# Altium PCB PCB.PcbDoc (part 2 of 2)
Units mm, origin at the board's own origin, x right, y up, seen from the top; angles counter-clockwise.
Board outline 40.89 x 35.18 mm, 4 copper layers (Top Layer, Signal Layer 1, Signal Layer 2, Bottom Layer), stack 1.554 mm thick; 53 components, 28 nets, 142 pads, 33 vias.
Unrouted connection lines stored in the file: 4.
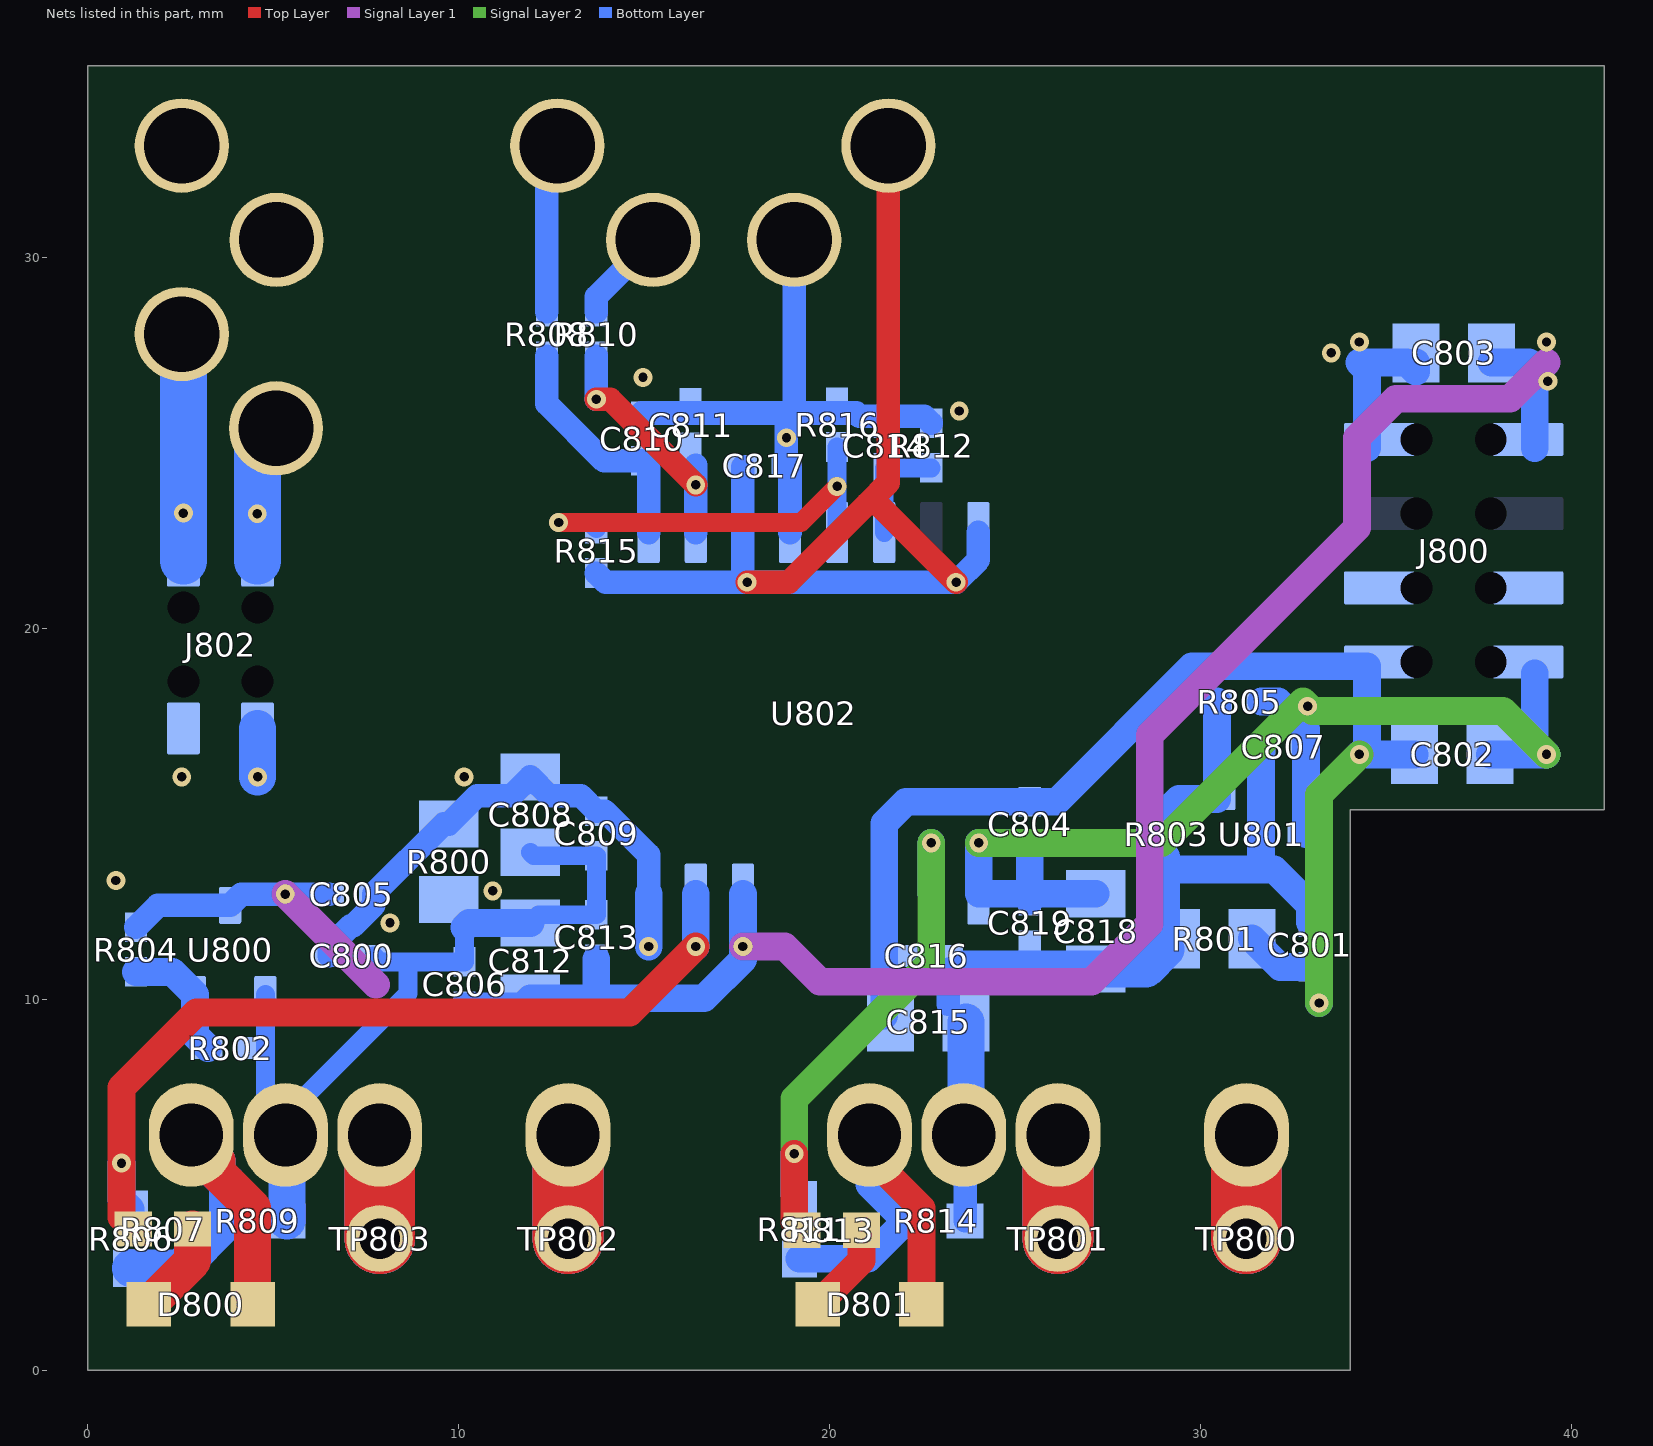
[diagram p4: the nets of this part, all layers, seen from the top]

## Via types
v1: diameter 0.508, hole 0.254, Top Layer to Bottom Layer, 33 vias

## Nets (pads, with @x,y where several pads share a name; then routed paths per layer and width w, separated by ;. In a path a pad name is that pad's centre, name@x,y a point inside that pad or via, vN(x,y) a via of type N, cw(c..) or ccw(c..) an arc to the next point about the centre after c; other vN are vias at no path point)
5Vp: C817.1 J802.1 J802.@4.582,20.571 pad.1@5.08,25.4 pad.1@21.59,33.02 R815.2 U802.3 U802.8 | length 34.7
  Top Layer w0.635: v1(17.78,21.249) 18.901,21.249 21.02,23.368 ; pad.1@21.59,33.02 21.59,23.938 21.02,23.368 ; v1(23.414,21.249) 21.295,23.368 21.02,23.368
  Bottom Layer w0.635: R815.2@13.716,21.498 13.965,21.249 v1(23.414,21.249) 24.017,21.852 U802.8@24.017,22.591 ; v1@17.667,21.39 U802.3@17.667,22.591 C817.1@17.667,24.363
  Bottom Layer w1.27: J802.1@4.582,21.831 pad.1@4.582,24.902
  other v1: 4.572,23.098
5Vs: J800.5 pad.1@35.83,21.098
+VA: C800.1 C803.1 C805.1 C808.1 C809.1 J800.1 pad.1@35.83,25.098 R800.2 U802.16 | length 18.5
  Bottom Layer w0.635: C800.1@6.512,11.176 6.512,11.408 7.098,11.993 7.167,11.993 7.712,12.538 C805.1@7.712,12.842 9.603,14.732 R800.2@9.738,14.732 10.5,15.494 11.43,15.494 C808.1@11.938,16.002 12.446,15.494 13.3,15.494 C809.1@13.716,15.078 13.948,15.078 15.127,13.899 U802.16@15.127,12.842
  Bottom Layer w0.75: v1(15.127,11.43) U802.16@15.127,12.842 ; J800.1@34.494,24.868 34.494,26.974 34.29,27.178 35.564,27.178 35.814,26.928 C803.1@35.814,27.178
  other v1: 8.154,12.065 10.15,16.002 33.528,27.432 34.29,27.727
+VB: C801.1 C802.1 C804.1 C815.1 C816.1 J800.7 pad.1@35.83,19.098 R801.2 U802.11 | length 33.7
  Signal Layer 2 w0.75: v1(33.203,9.906) 33.203,15.521 v1(34.29,16.608)
  Bottom Layer w0.75: C815.1@21.477,9.572 U802.11@21.477,12.842 21.477,14.746 22.063,15.332 C804.1@25.4,15.332 26.127,15.332 29.779,18.984 34.497,18.984 34.497,18.796 34.497,16.815 ; R801.2@31.394,11.643 32.156,10.881 C801.1@32.949,10.881 33.203,10.627 v1(33.203,9.906) ; v1(34.29,16.608) C802.1@35.776,16.608
-VA: C803.2 C805.2 C806.2 C812.2 C813.2 J800.2 pad.1@37.83,25.098 R804.1 U800.3 U802.14 | length 56.6
  Signal Layer 1 w0.75: v1(5.33,12.842) 7.772,10.4 ; v1(17.667,11.43) 18.796,11.43 19.746,10.48 27.064,10.48 28.636,12.052 28.636,17.132 34.224,22.72 34.224,25.146 35.276,26.198 38.352,26.198 39.332,27.178
  Bottom Layer w0.635: R804.1@1.303,11.945 1.895,12.537 U800.3@3.843,12.537 4.147,12.842 v1(5.33,12.842) C805.2@6.512,12.842
  Bottom Layer w0.75: C806.2@10.16,9.814 11.719,9.814 C812.2@11.938,10.033 13.716,10.033 ; C813.2@13.716,11.084 13.716,10.033 ; U802.14@17.667,12.842 v1(17.667,11.43) 17.667,11.083 16.617,10.033 13.716,10.033 ; C803.2@37.846,27.178 38.862,27.178 39.014,27.026 J800.2@39.014,24.868
  other v1: 0.762,13.208 39.37,26.67 39.332,27.727
-VB: C802.2 C804.2 C807.2 C818.2 C819.2 J800.8 pad.1@37.83,19.098 R805.1 U801.3 U802.9 | length 31.4
  Signal Layer 2 w0.75: v1(24.028,14.224) 28.956,14.224 32.766,18.034 33.02,17.78 38.16,17.78 v1(39.332,16.608)
  Bottom Layer w0.75: v1(24.028,14.224) 24.028,12.852 C819.2@25.4,12.852 ; C819.2@25.4,12.665 C819.2@25.4,12.852 ; C804.2@25.4,14.132 C819.2@25.4,12.852 ; C818.2@27.178,12.852 C819.2@25.4,12.852 ; R805.1@31.648,18.034 32.103,18.034 32.848,17.288 U801.3@32.848,14.455 ; C802.2@37.808,16.608 v1(39.332,16.608) ; 39.017,16.763 J800.8@39.017,18.796
  other v1: 32.893,17.907
Coma: C800.2 C806.1 C808.2 C809.2 C812.1 C813.1 pad.1@5.334,6.35 R800.1 R802.2 R809.1 U800.1 | length 22.9
  Bottom Layer w0.508: U800.1@4.793,10.137 4.793,6.891 pad.1@5.334,6.35 5.334,6.858 8.636,10.16 8.636,11.014 ; C800.2@7.712,11.176 7.874,11.014 8.636,11.014 ; 10.16,11.938 C806.1@10.16,11.014 8.636,11.014 ; C812.1@11.938,12.065 12.157,12.284 C813.1@13.716,12.284 C809.2@13.716,13.878 12.03,13.878 C808.2@11.938,13.97
  Bottom Layer w0.75: 10.16,11.938 10.287,12.065 C812.1@11.938,12.065
  Bottom Layer w1: pad.1@5.334,6.35 5.372,6.312 R809.1@5.372,4.031
  other v1: 10.922,12.929
Comb: C801.2 C807.1 C815.2 C816.2 C818.1 C819.1 pad.1@23.622,6.35 R801.1 R803.2 R814.1 U801.1 | length 21.7
  Bottom Layer w0.635: C815.2@23.206,9.875 23.206,10.82 ; R814.1@23.66,4.031 pad.1@23.66,6.312
  Bottom Layer w0.75: R801.1@29.075,11.355 R803.2@29.075,13.855 ; 29.425,13.505 U801.1@30.448,13.505 31.991,13.505 32.949,12.547 C801.2@32.949,12.081 ; 31.633,13.864 C807.1@31.633,16.821
  Bottom Layer w1: 23.622,10.82 C818.1@27.178,10.82 28.54,10.82 R801.1@29.075,11.355 ; pad.1@23.683,6.411 C815.2@23.683,9.398
NetC810_1: C810.1 R808.2 U802.1 | length 6.5
  Bottom Layer w0.635: R808.2@12.383,27.34 12.383,26.064 13.925,24.522 C810.1@14.947,24.522 15.127,24.342 U802.1@15.127,22.591
NetC811_1: C811.1 R810.2 U802.2 | length 6.6
  Top Layer w0.635: v1(13.716,26.184) 14.089,26.184 v1(16.397,23.876)
  Bottom Layer w0.635: v1(13.716,26.184) R810.2@13.716,27.34 ; U802.2@16.397,22.591 v1(16.397,23.876) 16.397,24.405
NetC814_1: C814.1 R812.2 U802.6 | length 3
  Bottom Layer w0.508: U802.6@21.477,22.591 21.477,24.322 C814.1@21.489,24.334 R812.2@22.747,24.334
NetD800_1: D800.1 R807.2 | length 2.5
  Top Layer w1: D800.1@1.648,1.778 2.832,2.962 R807.2@2.832,3.81
NetD801_1: D801.1 R813.2 | length 2.5
  Top Layer w0.75: D801.1@19.682,1.778 20.866,2.962 R813.2@20.866,3.777
NetR802_1: R802.1 R804.2 U800.2 | length 3.4
  Bottom Layer w0.75: R804.2@1.303,10.745 2.285,10.745 U800.2@2.893,10.137 2.893,9.041 R802.1@3.243,8.691
NetR803_1: R803.1 R805.2 U801.2 | length 4.1
  Bottom Layer w0.75: R803.1@29.075,15.055 29.425,15.405 U801.2@30.448,15.405 R805.2@30.448,18.034
NetR806_1: R806.1 R807.1 U802.15 | length 23.8
  Top Layer w0.75: R807.1@1.232,3.81 0.914,4.128 v1(0.914,5.588) 0.914,7.631 2.935,9.652 14.619,9.652 v1(16.397,11.43)
  Bottom Layer w0.75: v1(0.914,5.588) 0.914,4.599 R806.1@1.157,4.356 ; v1(16.397,11.43) U802.15@16.397,12.842
NetR811_1: R811.1 R813.1 U802.10 | length 14.5
  Top Layer w0.75: v1(19.05,5.842) 19.05,3.993 R813.1@19.266,3.777
  Signal Layer 2 w0.75: v1(19.05,5.842) 19.05,7.315 22.747,11.012 v1(22.747,14.224)
  Bottom Layer w0.75: R811.1@19.05,4.751 v1(19.05,5.842) ; U802.10@22.747,12.842 v1(22.747,14.224)
NetR815_1: R815.1 R816.2 U802.5 | length 11.3
  Top Layer w0.508: v1(12.7,22.86) 19.233,22.86 v1(20.207,23.834)
  Bottom Layer w0.508: v1(12.7,22.86) 13.554,22.86 R815.1@13.716,22.698 ; U802.5@20.207,22.591 v1(20.207,23.834) R816.2@20.207,24.895
PGND: C810.2 C811.2 C814.2 C817.2 J802.3 J802.@2.582,20.571 pad.1@2.54,27.94 pad.1@19.05,30.48 R812.1 R816.1 U802.4 | length 21.7
  Bottom Layer w0.635: C810.2@14.947,25.722 14.947,25.812 20.721,25.812 20.811,25.722 22.559,25.722 R812.1@22.747,25.534 ; C817.2@18.842,24.384 18.842,25.766 ; U802.4@18.937,22.591 C817.2@18.937,24.335 ; 19.05,25.974 pad.1@19.05,30.48
  Bottom Layer w1.27: J802.3@2.582,21.831 pad.1@2.582,27.898
  other v1: 2.582,23.114 18.842,25.146 23.5,25.866 14.974,26.771
SGND: J800.6 pad.1@37.83,21.098
VDA: pad.1@31.242,6.35 TP800.1 | length 11.2
  Top Layer w1.905: TP800.1@31.242,3.556 pad.1@31.242,6.35
  Signal Layer 1 w1.905: TP800.1@31.242,3.556 pad.1@31.242,6.35
  Signal Layer 2 w1.905: TP800.1@31.242,3.556 pad.1@31.242,6.35
  Bottom Layer w1.905: TP800.1@31.242,3.556 pad.1@31.242,6.35
VDB: pad.1@12.954,6.35 TP802.1 | length 11.2
  Top Layer w1.905: TP802.1@12.954,3.556 pad.1@12.954,6.35
  Signal Layer 1 w1.905: TP802.1@12.954,3.556 pad.1@12.954,6.35
  Signal Layer 2 w1.905: TP802.1@12.954,3.556 pad.1@12.954,6.35
  Bottom Layer w1.905: TP802.1@12.954,3.556 pad.1@12.954,6.35
Vg1: J802.2 J802.@4.582,18.571 pad.1@5.093,30.48 pad.1@12.663,33.02 R808.1 | length 5.5
  Bottom Layer w0.635: R808.1@12.383,28.54 pad.1@12.383,32.74
  Bottom Layer w1: v1(4.582,16.002) J802.2@4.582,17.311
Vg2: J802.4 J802.@2.582,18.571 pad.1@2.54,33.02 pad.1@15.247,30.48 R810.1 | length 2.6
  Bottom Layer w0.635: R810.1@13.716,28.54 13.716,28.949 pad.1@15.247,30.48
  other v1: 2.54,16.002
VGA: D800.2 pad.1@2.794,6.35 R806.2 R809.2 | length 11.1
  Top Layer w1: pad.1@2.794,6.35 3.491,5.653 3.491,5.333 4.448,4.376 D800.2@4.448,1.778
  Bottom Layer w1: R806.2@1.157,2.756 2.497,2.756 R809.2@3.772,4.031 3.772,5.052 3.491,5.333 3.491,5.653 pad.1@2.794,6.35
VGB: D801.2 pad.1@21.082,6.35 R811.2 R814.2 | length 10.6
  Top Layer w0.75: pad.1@21.082,5.772 22.482,4.372 D801.2@22.482,1.778
  Bottom Layer w0.75: R811.2@19.191,3.01 21.039,3.01 R814.2@22.06,4.031 21.082,5.009 pad.1@21.082,6.35
VSA: pad.1@26.162,6.35 TP801.1 | length 11.2
  Top Layer w1.905: TP801.1@26.162,3.556 pad.1@26.162,6.35
  Signal Layer 1 w1.905: TP801.1@26.162,3.556 pad.1@26.162,6.35
  Signal Layer 2 w1.905: TP801.1@26.162,3.556 pad.1@26.162,6.35
  Bottom Layer w1.905: TP801.1@26.162,3.556 pad.1@26.162,6.35
VSB: pad.1@7.874,6.35 TP803.1 | length 11.2
  Top Layer w1.905: TP803.1@7.874,3.556 pad.1@7.874,6.35
  Signal Layer 1 w1.905: TP803.1@7.874,3.556 pad.1@7.874,6.35
  Signal Layer 2 w1.905: TP803.1@7.874,3.556 pad.1@7.874,6.35
  Bottom Layer w1.905: TP803.1@7.874,3.556 pad.1@7.874,6.35
pads on no net: J800.3 J800.4 U802.7

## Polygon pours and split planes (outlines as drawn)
-VB on Bottom Layer "-VB" (solid, pour order 72): 31.598,18.288 33.274,18.288 33.782,17.78 33.782,14.322 33.43,13.97 32.634,13.97 32.283,14.32 32.283,17.081 31.648,17.716
-VB on Bottom Layer "-VB" (solid, pour order 70): 37.592,19.558 37.084,19.05 37.084,15.621 37.592,15.113 39.878,15.113 40.386,15.621 40.386,19.05 39.878,19.558
+VB on Bottom Layer "+VB" (solid, pour order 64): 22.098,8.382 20.828,8.382 20.574,8.636 20.574,16.255 21.082,16.763 26.122,16.763 26.67,17.311 26.67,19.294 27.188,19.812 35.814,19.812 36.322,19.304 36.322,15.621 35.814,15.113 34.923,15.113 34.036,16 34.036,17.907 33.401,18.542 30.16,18.542 29.779,18.161 29.798,18.142 29.798,16.082
Comb on Bottom Layer "COMB" (solid, pour order 62): 23.116,3.302 22.862,3.556 22.86,3.556 22.86,4.031 22.86,11.472 23.128,11.74 26.276,11.74 31.356,16.821 32.151,16.821 32.848,16.123 32.848,14.185 33.528,13.505 33.528,11.759 33.249,11.481 31.293,11.481 27.94,8.128 25.4,8.128 24.638,7.366 24.638,3.56 24.384,3.306
+VB on Bottom Layer "+VB" (solid, pour order 60): 30.988,12.446 30.734,12.192 30.734,10.414 31.496,9.652 33.528,9.652 33.782,9.906 33.782,10.668 32.004,12.446
-VB on Bottom Layer "-VB" (solid, pour order 58): 23.876,12.192 27.649,12.192 27.94,12.483 27.94,13.716 27.114,14.541 24.182,14.541 23.876,14.235
VGB on Bottom Layer "VGB" (solid, pour order 56): 18.542,3.556 18.288,3.302 18.288,1.778 18.542,1.524 21.844,1.524 22.606,2.286 22.606,4.826 22.098,5.334 22.098,6.999 21.477,7.62 20.758,7.62 20.066,6.928 20.066,4.106 19.516,3.556
VGA on Bottom Layer "VGA" (solid, pour order 54): 2.032,7.874 1.778,7.62 1.778,3.589 1.524,3.335 1.232,3.335 1.016,3.119 1.016,2.286 1.27,2.032 3.893,2.032 4.147,2.286 4.147,5.312 3.048,6.411 3.048,7.62 2.794,7.874
-VA on Bottom Layer "-VA" (solid, pour order 46): 9.906,8.89 9.652,9.144 9.652,10.16 9.906,10.414 12.192,10.414 12.954,11.176 17.007,11.176 17.272,11.441 17.272,13.247 17.487,13.462 17.855,13.462 17.855,13.387 18.034,13.208 18.034,10.414 16.51,8.89
+VA on Bottom Layer "+VA" (solid, pour order 44): 15.24,11.176 15.494,11.43 15.494,15.755 14.993,16.256 9.652,16.256 8.128,14.732 8.128,13.97 5.893,11.735 5.893,11.084 6.101,10.876 13.716,10.876 14.016,11.176
Coma on Bottom Layer "Coma" (solid, pour order 42): 5.093,3.302 4.839,3.556 4.826,3.556 4.826,5.08 4.443,5.463 4.443,6.479 4.318,6.604 4.318,10.185 4.733,10.6 6.927,10.6 9.393,13.066 10.011,13.066 11.281,14.336 13.477,14.336 13.97,13.843 13.97,12.288 13.037,11.355 11.401,11.355 10.46,10.414 9.319,10.414 6.373,7.467 6.373,3.583 6.096,3.306
-VA on Bottom Layer "-VA" (solid, pour order 40): 0.752,13.716 0.508,13.472 0.508,11.684 0.762,11.43 5.294,11.43 6.31,12.446 6.762,12.446 6.858,12.542 6.858,13.462 6.604,13.716
Vg2 on Bottom Layer "Vg2" (solid, pour order 0): 3.048,15.748 2.794,15.494 0.762,15.494 0.254,16.002 0.254,33.274 1.524,34.544 3.545,34.544 4.053,34.036 4.053,32.514 1.482,29.943 1.482,19.727 3.048,18.161
5Vp on Bottom Layer "5Vp" (solid, pour order 6): 6.096,26.924 6.604,26.416 6.604,21.577 5.093,20.066 4.026,20.066 3.772,20.32 3.772,26.114 4.582,26.924
PGND on Bottom Layer "PGND" (solid, pour order 14): 3.556,29.471 4.064,28.963 4.064,28.086 4.064,26.694 3.556,26.186 3.556,20.314 3.308,20.066 2.017,20.066 1.763,20.32 1.763,26.191 1.27,26.683 1.27,28.978 1.763,29.471
PGND on Bottom Layer "PGND" (solid, pour order 26): 17.018,32.004 16.764,31.75 16.764,29.968 14.478,27.682 14.478,25.795 14.873,25.4 23.465,25.4 23.648,25.582 23.648,28.422 20.066,32.004
-VA on Bottom Layer "-VA" (solid, pour order 74): 39.878,24.384 40.378,24.884 40.386,27.94 39.878,28.448 37.338,28.448 37.084,28.194 37.084,24.638 37.338,24.384
+VA on Bottom Layer "+VA" (solid, pour order 76): 36.322,28.451 36.576,28.197 36.576,24.892 36.068,24.384 33.541,24.384 33.02,24.905 33.02,27.94 33.528,28.448
-VB on Signal Layer 2 "-VB" (solid, pour order 68): 39.624,15.487 39.878,15.741 39.878,17.78 39.116,18.542 37.846,18.542 36.322,20.066 29.576,20.066 26.274,16.764 23.876,16.764 23.622,16.51 23.622,13.712 23.876,13.458 29.178,13.458 31.242,15.521
+VB on Signal Layer 2 "+VB" (solid, pour order 66): 32.848,17.018 31.478,15.648 31.478,10.178 32.004,9.652 33.528,9.652 33.782,9.906 33.782,15.24 34.036,15.494 34.544,15.494 34.798,15.748 34.798,16.764 34.544,17.018
-VA on Signal Layer 2 "-VA" (solid, pour order 52): 0.762,13.716 0.508,13.462 0.508,11.929 0.756,11.681 5.336,11.681 5.593,11.938 5.588,11.943 5.588,13.458 5.33,13.716
+VA on Signal Layer 2 "+VA" (solid, pour order 50): 7.62,11.726 7.366,11.98 7.366,13.208 8.128,13.97 8.128,14.392 9.992,16.256 10.668,16.256 10.922,16.002 10.922,14.646 8.636,12.36 8.636,12.065 8.297,11.726
Coma on Signal Layer 2 "Coma" (solid, pour order 48): 5.093,3.237 4.839,3.491 4.826,3.491 4.826,5.015 4.443,5.398 4.443,6.414 4.318,6.539 4.318,8.669 6.184,10.535 6.927,10.535 9.393,13.001 10.011,13.001 10.218,13.208 11.318,13.208 11.684,12.841 11.684,12.146 9.887,10.349 9.319,10.349 6.373,7.402 6.373,3.518 6.096,3.241
Vg2 on Signal Layer 2 "Vg2" (solid, pour order 2): 3.048,15.739 2.794,15.485 0.762,15.485 0.254,15.993 0.254,33.265 1.524,34.535 3.545,34.535 4.053,34.027 4.053,32.505 1.482,29.934 1.482,19.719 3.048,18.152
5Vp on Signal Layer 2 "5Vp" (solid, pour order 12): 6.096,26.924 6.604,26.416 6.604,21.577 5.093,20.066 4.026,20.066 3.772,20.32 3.772,26.114 4.582,26.924
PGND on Signal Layer 2 "PGND" (solid, pour order 20): 3.556,29.471 4.064,28.963 4.064,28.086 4.064,26.694 3.556,26.186 3.556,20.314 3.308,20.066 2.017,20.066 1.763,20.32 1.763,26.191 1.27,26.683 1.27,28.978 1.763,29.471
5Vp on Signal Layer 2 "5Vp" (solid, pour order 24): 20.574,34.544 20.066,34.036 20.066,23.302 19.125,22.361 17.281,22.361 17.018,22.098 17.018,21.082 17.272,20.828 23.622,20.828 23.876,21.082 23.876,34.036 23.368,34.544
PGND on Signal Layer 2 "PGND" (solid, pour order 30): 17.018,32.004 16.764,31.75 16.764,29.968 14.478,27.682 14.478,25.795 14.873,25.4 23.465,25.4 23.648,25.582 23.648,28.422 20.066,32.004
NetR811_1 on Signal Layer 2 "R811_1" (solid, pour order 78): 22.098,14.732 21.844,14.478 21.844,11.671 18.288,8.115 18.288,5.588 18.542,5.334 19.558,5.334 19.812,5.588 19.812,7.14 23.368,10.696 23.368,14.48 23.116,14.732
-VA on Signal Layer 1 "-VA" (solid, pour order 36): 1.125,14.097 0.506,13.479 0.506,12.702 0.508,11.671 3.035,9.144 19.812,9.144 20.32,9.652 27.686,9.652 30.48,12.446 30.48,18.288 34.804,22.612 34.804,24.898 35.56,25.654 37.084,25.654 37.338,25.4 37.338,24.384 37.592,24.13 40.132,24.13 40.64,24.638 40.64,27.94 40.132,28.448 35.657,28.448 30.226,23.017 30.226,21.457 27.178,18.409 27.178,14.097 25.133,12.052 21.616,12.052 19.572,14.097
Vg1 on Signal Layer 1 "Vg1" (solid, pour order 4): 6.096,32.004 6.599,31.501 6.604,29.438 6.122,28.956 4.572,28.956 3.81,29.718 2.038,29.718 1.784,29.464 1.482,29.162 1.482,19.727 2.921,18.288 5.08,18.288 5.33,18.034 5.33,15.998 4.826,15.494 0.753,15.494 0.254,15.993 0.254,31.505 0.753,32.004
5Vp on Signal Layer 1 "5Vp" (solid, pour order 10): 6.096,26.924 6.604,26.416 6.604,21.577 5.093,20.066 4.026,20.066 3.772,20.32 3.772,26.114 4.582,26.924
PGND on Signal Layer 1 "PGND" (solid, pour order 18): 3.556,29.471 4.064,28.963 4.064,28.086 4.064,26.694 3.556,26.186 3.556,20.314 3.308,20.066 2.017,20.066 1.763,20.32 1.763,26.191 1.27,26.683 1.27,28.978 1.763,29.471
PGND on Signal Layer 1 "PGND" (solid, pour order 28): 17.018,32.004 16.764,31.75 16.764,29.968 14.478,27.682 14.478,25.795 14.873,25.4 23.465,25.4 23.648,25.582 23.648,28.422 20.066,32.004
+VA on Top Layer "+VA" (solid, pour order 38): 34.798,28.448 35.306,27.94 35.306,25.394 34.804,24.892 34.804,22.612 30.48,18.288 30.48,12.446 27.686,9.652 20.066,9.652 17.78,11.938 16.256,11.938 14.478,10.16 7.112,10.16 6.122,11.15 6.122,13.351 6.487,13.716 7.874,13.716 8.154,13.996 8.154,14.758 9.652,16.256 17.413,16.256 21.604,12.065 25.121,12.065 27.178,14.122 27.178,18.288 30.226,21.336 30.226,22.62 33.02,25.414 33.02,27.94 33.531,28.451
Vg1 on Top Layer "Vg1" (solid, pour order 34): 6.096,32.027 6.599,31.525 6.604,29.461 6.122,28.979 4.572,28.979 3.81,29.741 2.038,29.741 1.784,29.487 1.482,29.185 1.482,19.751 2.921,18.311 5.08,18.311 5.33,18.057 5.33,16.021 4.826,15.517 0.753,15.517 0.254,16.017 0.254,31.528 0.753,32.027
5Vp on Top Layer "5Vp" (solid, pour order 8): 6.096,26.924 6.604,26.416 6.604,21.577 5.093,20.066 4.026,20.066 3.772,20.32 3.772,26.114 4.582,26.924
PGND on Top Layer "PGND" (solid, pour order 16): 3.556,29.471 4.064,28.963 4.064,28.086 4.064,26.694 3.556,26.186 3.556,20.314 3.308,20.066 2.017,20.066 1.763,20.32 1.763,26.191 1.27,26.683 1.27,28.978 1.763,29.471
5Vp on Top Layer "5Vp" (solid, pour order 22): 20.574,34.544 20.066,34.036 20.066,23.302 19.125,22.361 17.281,22.361 17.018,22.098 17.018,21.082 17.272,20.828 23.622,20.828 23.876,21.082 23.876,34.036 23.368,34.544
NetR806_1 on Top Layer "R806_1" (solid, pour order 32): 0.508,3.048 0.254,3.302 0.254,8.89 1.524,10.16 14.478,10.16 16.256,11.938 16.764,11.938 17.018,11.684 17.018,10.414 15.494,8.89 3.302,8.89 1.778,7.366 1.778,3.339 1.487,3.048

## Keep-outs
Keep-Out Layer:
  text ".Layer_Name" at 14.656,-21.806 h1.52

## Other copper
Top Layer:
  text ".Layer_Name" at 14.656,-21.806 h1.52
Bottom Layer:
  text ".Layer_Name" at 14.656,-21.806 h1.52

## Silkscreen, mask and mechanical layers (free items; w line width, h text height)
Top Overlay:
  lines w0.254: 0.538,-0.302 3.332,-0.302 ; 1.016,14.097 7.874,14.097 7.874,21.336 7.112,21.336 7.112,14.986 1.016,14.986 1.016,14.097 ; 7.112,22.352 7.112,35.179 7.874,35.179 7.874,22.352 7.112,22.352 ; 10.191,17.272 26.162,17.272 26.162,23.368 25.146,23.368 25.146,18.288 10.191,18.288 10.191,17.272
  text "PMP22002 RevA" at 5.842,8.467 h2.75
  text ".Layer_Name" at 14.656,-21.806 h1.52
Bottom Overlay:
  lines w0.254: 0.254,14.732 0.254,11.662 0.508,11.408 ; 1.016,8.89 1.143,8.89 2.032,9.779 ; 1.27,1.524 1.524,1.27 2.794,1.27 ; 3.958,13.513 5.359,13.513 5.588,13.284 ; 8.154,17.526 9.964,17.526 9.964,17.78 9.964,19.05 ; 9.059,17.526 9.059,16.939 9.488,16.51 10.5,16.51 ; 24.892,23.876 25.421,24.405 26.626,24.405 ; 26.279,16.002 26.924,16.647 26.924,16.763 ; 29.21,31.172 29.292,31.172 31.394,33.274 37.084,33.274 39.014,31.344 39.014,29.927 35.007,29.927 32.766,27.686 29.972,27.686 ; 30.48,27.686 30.48,19.492 30.988,18.984
  text ".Layer_Name" at 14.656,-21.806 h1.52
Top Paste:
  text ".Layer_Name" at 14.656,-21.806 h1.52
Bottom Paste:
  text ".Layer_Name" at 14.656,-21.806 h1.52
Top Solder:
  text ".Layer_Name" at 14.656,-21.806 h1.52
  text ".Layer_Name" at 14.656,-21.806 h1.52
Bottom Solder:
  text ".Layer_Name" at 14.656,-21.806 h1.52
Drill Guide:
  text ".Layer_Name" at 14.656,-21.806 h1.52
M1 Board Outline:
  circle w0.254: c26.162,29.007 r3.556
  lines w0.254: 0,14.097 0,35.179 7.874,35.179 ; 0,14.097 0,0 34.036,0 34.036,15.113 40.894,15.113 40.894,35.179 7.874,35.179 ; 0,14.097 7.874,14.097 7.874,25.451 ; 7.874,25.451 ccw(c7.874,29.007) 7.874,32.563 ; 7.874,25.451 7.874,32.563 ; 7.874,32.563 7.874,35.179
  text ".Layer_Name" at 14.656,-21.806 h1.52
M2 Board Dimensions:
  rectangle: 3.175,-10.16 12.7,-6.985
  rectangle: 0,-6.985 3.175,-3.81
  lines w0.178: 0,-6.985 25.4,-6.985 ; 3.175,-10.16 3.175,-3.81 ; 6.35,-10.16 6.35,-3.81 ; 12.7,-10.16 12.7,-3.81 ; 19.05,-10.16 19.05,-3.81 ; 0,-10.16 0,-3.81 25.4,-3.81 25.4,-10.16 0,-10.16
  text ".Layer_Name" at 14.656,-21.806 h1.52
M3 3D STEP Top:
  text ".Layer_Name" at 14.656,-21.806 h1.52
M4 3D STEP Bottom:
  text ".Layer_Name" at 14.656,-21.806 h1.52
M5 Assembly Top:
  lines w0.254: -7.417,-23.626 160.223,-23.626 ; -7.417,-18.462 160.274,-18.462 ; -7.417,-13.297 -7.417,-28.791 94.31,-28.791 160.274,-28.791 160.274,-13.297 -7.404,-13.297 -7.404,-28.791 32.614,-28.791 ; 55.194,-28.791 55.194,-13.297 ; 87.376,-18.462 87.376,-13.297 ; 108.712,-18.462 108.712,-13.297 ; 124.511,-28.956 124.511,-23.804
  text "COMPONENTS MARKED 'DNP' SHOULD NOT BE POPULATED." at 29.299,-8.09 h1.52
  text "ASSEMBLY VARIANT:" at 29.286,-11.024 h1.52
  text ".VariantName" at 55.601,-11.024 h1.52
  text "PCB VIEWED FROM TOP SIDE" at -5.804,-16.654 h1.52
  text "BOARD #:" at 57.099,-16.654 h1.52
  text ".PRJ_Number" at 70.955,-16.654 h1.52
  text "REV:" at 92.405,-16.654 h1.52
  text ".PCB_Rev" at 99.809,-16.654 h1.52
  text "SVN REV:" at 113.69,-16.654 h1.52
  text ".VersionControl_RevNumber" at 126.543,-16.654 h1.52
  text "TID #:" at 57.099,-21.819 h1.52
  text ".TID" at 70.955,-21.819 h1.52
  text "PLOT NAME =" at -5.804,-27.034 h1.52
  text ".plot_File_Name" at 14.656,-27.034 h1.52
  text "GENERATED    :" at 57.15,-27.034 h1.52
  text ".Print_Date" at 79.235,-27.034 h1.52
  text ".Print_Time" at 97.752,-27.034 h1.52
  text "TEXAS INSTRUMENTS" at 129.87,-27.034 h1.52
M6 Assembly Bottom:
  lines w0.254: -7.429,-18.474 160.261,-18.474 ; -7.379,-23.639 160.261,-23.639 ; 28.334,-28.969 28.334,-23.817 ; 44.133,-18.474 44.133,-13.31 ; 65.468,-18.474 65.468,-13.31 ; 97.65,-28.804 97.65,-13.31 ; 120.231,-28.804 160.249,-28.804 160.249,-13.31 -7.429,-13.31 -7.429,-28.804 58.534,-28.804 160.261,-28.804 160.261,-13.31
  text "COMPONENTS MARKED 'DNP' SHOULD NOT BE POPULATED." at 154.991,-8.077 h1.52
  text ".VariantName" at 128.473,-11.024 h1.52
  text "ASSEMBLY VARIANT:" at 154.864,-11.024 h1.52
  text ".VersionControl_RevNumber" at 26.302,-16.667 h1.52
  text "SVN REV:" at 39.154,-16.667 h1.52
  text ".PCB_Rev" at 53.035,-16.667 h1.52
  text "REV:" at 60.439,-16.667 h1.52
  text ".PRJ_Number" at 81.89,-16.667 h1.52
  text "BOARD #:" at 95.745,-16.667 h1.52
  text "PCB VIEWED FROM BOTTOM SIDE" at 158.648,-16.667 h1.52
  text ".TID" at 81.89,-21.831 h1.52
  text "TID #:" at 95.745,-21.831 h1.52
  text "TEXAS INSTRUMENTS" at 22.974,-27.047 h1.52
  text ".Print_Time" at 55.093,-27.047 h1.52
  text ".Print_Date" at 73.609,-27.047 h1.52
  text "GENERATED    :" at 95.694,-27.047 h1.52
  text ".plot_File_Name" at 138.189,-27.047 h1.52
  text "PLOT NAME =" at 158.648,-27.047 h1.52
M9 Title Sheet:
  drawing of 57 lines, arcs and shapes, not listed
  text "1" at 18.792,204.127 h1.78
  text "2" at 82.182,204.127 h1.78
  text "3" at 145.411,204.127 h1.78
  text "4" at 209.08,204.127 h1.78
  text "5" at 272.555,204.127 h1.78
  text "6" at 336.182,204.127 h1.78
  text "A" at -10.579,175.095 h1.78
  text "A" at 365.341,175.095 h1.78
  text "B" at -10.579,114.643 h1.78
  text "B" at 365.341,114.643 h1.78
  text "C" at -10.579,54.318 h1.78
  text "C" at 365.341,54.318 h1.78
  text "PROJECT TITLE:" at 288.125,7.048 h1.14
  text ".PRJ_Title" at 289.395,3.662 h1.78
  text "DESIGNED FOR:" at 288.125,-0.597 h1.14
  text ".PRJ_Customer" at 289.395,-4.153 h1.78
  text "D" at -10.579,-5.88 h1.78
  text "D" at 365.341,-5.88 h1.78
  text "FILE NAME:" at 288.125,-8.217 h1.14
  text ".PCB_File_Name_No_Path" at 289.395,-11.265 h1.78
  text "Texas Instruments (TI) and/or its licensors do not warrant the accuracy or completeness of this specification" at 161.9,-15.376 h1.14
  text "ENGINEER:" at 288.125,-15.583 h1.14
  text "LAYOUT BY:" at 326.352,-15.583 h1.14
  text "or any information contained therein. TI and/or its licensors do not warrant that this design will meet" at 160.757,-18.237 h1.14
  text ".PRJ_Engineer" at 289.395,-19.52 h1.78
  text ".PCB_Layout" at 327.635,-19.52 h1.78
  text "the specifications, will be suitable for your application or fit for any particular purpose, or will operate in" at 160.757,-21.099 h1.14
  text ".Layer_Name" at 14.656,-21.806 h1.52
  text "ALTIUM DESIGNER VERSION:" at 326.352,-23.457 h1.14
  text "an implementation. TI and/or its licensors do not warrant that the design is production worthy. You should" at 160.757,-23.961 h1.14
  text "completely validate and test your design implementation to confirm the system functionality for your application." at 161.9,-26.822 h1.14
  text ".print_Scale" at 289.395,-26.843 h1.78
  text ".Application_BuildNumber" at 327.635,-26.843 h1.78
  text "1" at 18.792,-32.093 h1.78
  text "2" at 82.182,-32.093 h1.78
  text "3" at 145.411,-32.093 h1.78
  text "4" at 209.08,-32.093 h1.78
  text "5" at 272.555,-32.093 h1.78
  text "6" at 336.182,-32.093 h1.78
M10 Fab Notes:
  drawing of 189 lines, arcs and shapes, not listed
  text "DESIGN INFORMATION" at 314.503,161.447 h1.52
  text "MIN. TRACK WIDTH:" at 298.131,158.091 h1.52
  text "8" at 325.976,158.091 h1.52
  text "MIL" at 329.907,158.091 h1.52
  text "MIN. CLEARANCE:" at 298.131,154.938 h1.52
  text "0.2" at 324.452,154.938 h1.52
  text "mm" at 329.907,154.938 h1.52
  text "MIN. VIA PAD SIZE:" at 298.131,151.785 h1.52
  text "24" at 325.214,151.785 h1.52
  text "MIL" at 329.907,151.785 h1.52
  text "0.05mm (2MIL)" at 315.784,148.486 h1.52
  text "MINIMUM ANNULAR RING" at 289.769,148.277 h1.52
  text "EXTERNAL" at 333.768,148.277 h1.52
  text "PER" at 294.849,145.48 h1.52
  text "IPC-D-275 CLASS 2 LEVEL C" at 300.437,145.48 h1.52
  text "MIL, HOLES" at 338.238,142.928 h1.52
  text "+/-" at 328.27,142.709 h1.52
  text "+/-" at 349.961,142.709 h1.52
  text "REGISTRATION TOLERANCES:" at 289.769,142.682 h1.52
  text "METAL" at 320.243,142.682 h1.52
  text "5" at 334.879,142.683 h1.52
  text "3" at 356.037,142.683 h1.52
  text "MIL" at 358.99,142.682 h1.52
  text "HOLE SIZE TOLERANCE (UNLESS OTHERWISE SPECIFIED):" at 289.769,140.185 h1.52
  text "+/-" at 349.961,140.112 h1.52
  text "3" at 356.037,140.085 h1.52
  text "MIL" at 358.99,140.085 h1.52
  text "MATERIAL:" at 287.87,136.589 h1.52
  text "FR-4 High Tg" at 312.926,133.324 h1.52
  text "X" at 309.257,133.122 h1.52
  text "FR-408" at 298.563,133.007 h1.52
  text "OTHER" at 336.358,133.007 h1.52
  text "62 MIL (1.6mm) +/-10%" at 306.694,129.374 h1.52
  text "X" at 303.643,129.312 h1.52
  text "THICKNESS:" at 289.769,129.165 h1.52
  text "OTHER" at 339.33,129.165 h1.52
  text "TOLERANCE:" at 289.769,125.652 h1.52
  text "X" at 311.314,125.652 h1.52
  text "ANSI IPC-6012 TYPE 3 CLASS 2" at 315.836,125.652 h1.52
  text "OTHER +/-" at 315.835,121.989 h1.52
  text "BOW & TWIST:" at 289.769,118.302 h1.52
  text "X" at 311.314,118.302 h1.52
  text "ANSI IPC-6012 TYPE 3 CLASS 2" at 315.836,118.302 h1.52
  text "OTHER +/-" at 315.835,114.576 h1.52
  text "DRILLING:" at 287.87,111.258 h1.52
  text "NC_DRILL FILES" at 332.599,108.586 h1.52
  text "REFERENCE:" at 289.769,108.486 h1.52
  text "X" at 306.463,108.484 h1.52
  text "AS SHOWN" at 310.984,108.486 h1.52
  text "X" at 329.348,108.486 h1.52
  text "OTHER" at 340.168,104.873 h1.52
  text "PTH COPPER THICKNESS:" at 289.761,104.783 h1.52
  text "X" at 318.697,104.783 h1.52
  text "20-30 um" at 321.948,104.783 h1.52
  text "BOARD FINISH:" at 287.87,101.034 h1.52
  text "SILKSCREEN:" at 291.812,98.237 h1.52
  text "X" at 316.14,98.237 h1.52
  text "TOP" at 319.112,98.237 h1.52
  text "X" at 329.094,98.237 h1.52
  text "BOTTOM" at 332.091,98.237 h1.52
  text "SILKSCREEN COLOR:" at 291.812,94.295 h1.52
  text "X" at 316.115,94.295 h1.52
  text "WHITE" at 319.112,94.295 h1.52
  text "OTHER" at 332.091,94.295 h1.52
  text "X" at 319.442,90.652 h1.52
  text "GREEN" at 322.439,90.652 h1.52
  text "OTHER" at 338.136,90.652 h1.52
  text "SOLDER RESIST COLOR:" at 291.812,90.477 h1.52
  text "X" at 319.442,86.734 h1.52
  text "MATTE" at 322.439,86.734 h1.52
  text "SEMI-GLOSS" at 338.125,86.717 h1.52
  text "IMMERSION GOLD (ENIG)" at 314.819,82.345 h1.52
  text "ENEPIG" at 348.793,82.162 h1.52
  text "SURFACE FINISH:" at 287.87,82.136 h1.52
  text "X" at 310.298,82.136 h1.52
  text "IMM. TIN/SILVER OR EQUIV" at 296.24,78.649 h1.52
  text "OTHER" at 332.599,78.549 h1.52
  text "ARRAY/PANEL:" at 287.87,74.602 h1.52
  text "CUT AND TRIM PER M1 BOARD OUTLINE" at 314.819,74.393 h1.52
  text "N.C. ROUTE" at 314.819,70.94 h1.52
  text "X" at 332.295,70.94 h1.52
  text "V. SCORE" at 336.816,70.94 h1.52
  text "CERTIFICATION:" at 287.87,67.66 h1.52
  text "MATERIALS AND WORKMANSHIP FOR ALL PCBS" at 306.285,67.66 h1.52
  text "TO MEET OR EXCEED THE REQUIREMENTS OF:" at 306.285,65.271 h1.52
  text "X" at 297.078,62.003 h1.52
  text "ANSI IPC-A-600F CLASS ->" at 300.329,62.003 h1.52
  text "X" at 342.188,62.003 h1.52
  text "2" at 344.982,62.003 h1.52
  text "1" at 336.981,61.965 h1.52
  text "3" at 353.973,61.965 h1.52
  text "X" at 317.702,58.252 h1.52
  text "RoHS" at 320.953,58.252 h1.52
  text "OTHER" at 337.321,58.252 h1.52
  text "PER ORDER" at 347.407,58.252 h1.52
  text "ALL BOARDS MUST MEET OR EXCEED UL94-V0 REQUIREMENTS." at 288.569,54.345 h1.52
  text "PCB MUST BEAR THE UL94V-0 UL REGISTERED MATERIAL ID NUMBER" at 288.569,51.397 h1.52
  text "ADDITIONAL REQUIREMENTS:" at 287.87,47.094 h1.52
  text "MICROSECTION:" at 289.769,44.373 h1.52
  text "YES" at 312.775,44.373 h1.52
  text "REQUIRED" at 334.657,40.707 h1.52
  text "BARE BOARD ELEC. TEST:" at 289.769,40.634 h1.52
  text "NONE" at 322.935,40.634 h1.52
  text "X" at 331.66,40.634 h1.52
  text "PER ORDER" at 349.693,40.634 h1.52
  text "XX MIL VIAS REQUIRE NON-CONDUCTIVE FILL AND PLANARIZE" at 294.04,35.428 h1.5
  text "XX MIL VIAS REQUIRE CONDUCTIVE FILL AND PLANARIZE" at 294.243,32.787 h1.52
  text "OUTER XX MIL TRACES REQUIRE 50 OHM SINGLE-ENDED IMPEDANCE" at 294.218,28.637 h1.47
  text "LAYER 2 & 3 (INNER LAYERS) XX MIL WIDE, XX MIL SPACE / TRACES REQUIRE 100 OHM DIFFERENTIAL IMPEDANCE" at 294.015,22.65 h1.52
  text ".Layer_Name" at 14.656,-21.806 h1.52
M11 Gerber Information:
  lines w0.254: -7.417,-23.626 160.223,-23.626 ; -7.417,-18.462 160.274,-18.462 ; -7.417,-13.297 -7.417,-28.791 94.31,-28.791 160.274,-28.791 160.274,-13.297 -7.404,-13.297 -7.404,-28.791 32.614,-28.791 ; 55.194,-28.791 55.194,-13.297 ; 87.376,-18.462 87.376,-13.297 ; 108.712,-18.462 108.712,-13.297 ; 124.511,-28.956 124.511,-23.804
  text "ALL ARTWORK VIEWED FROM TOP SIDE" at -5.804,-16.654 h1.52
  text "BOARD #:" at 57.099,-16.654 h1.52
  text ".PRJ_Number" at 70.955,-16.654 h1.52
  text "REV:" at 92.405,-16.654 h1.52
  text ".PCB_Rev" at 99.809,-16.654 h1.52
  text "SVN REV:" at 113.69,-16.654 h1.52
  text ".VersionControl_RevNumber" at 126.543,-16.654 h1.52
  text "LAYER NAME =" at -5.804,-21.806 h1.52
  text "TID #:" at 57.099,-21.819 h1.52
  text ".TID" at 70.955,-21.819 h1.52
  text "PLOT NAME =" at -5.804,-27.034 h1.52
  text ".plot_File_Name" at 14.656,-27.034 h1.52
  text "GENERATED    :" at 57.15,-27.034 h1.52
  text ".Print_Date" at 79.235,-27.034 h1.52
  text ".Print_Time" at 97.752,-27.034 h1.52
  text "TEXAS INSTRUMENTS" at 129.87,-27.034 h1.52
M12 Stackup:
  drawing of 295 lines, arcs and shapes, not listed
  text "Layer" at 167.903,195.326 h1.52
  text "Name" at 178.315,195.326 h1.52
  text "Material" at 202.184,195.326 h1.52
  text "Thickness" at 224.022,195.326 h1.52
  text "Constant" at 240.528,195.326 h1.52
  text "Board Layer Stack" at 255.002,195.326 h1.52
  text "1" at 167.903,192.278 h1.52
  text "Top Overlay" at 178.315,192.278 h1.52
  text "2" at 167.903,189.23 h1.52
  text "Top Solder" at 178.315,189.23 h1.52
  text "Solder Resist" at 202.184,189.23 h1.52
  text "0.40mil" at 224.022,189.23 h1.52
  text "3.5" at 240.528,189.23 h1.52
  text "3" at 167.903,186.182 h1.52
  text "Top Layer" at 178.315,186.182 h1.52
  text "Copper" at 202.184,186.182 h1.52
  text "1.40mil" at 224.022,186.182 h1.52
  text "4" at 167.903,183.134 h1.52
  text "Dielectric 3" at 178.315,183.134 h1.52
  text "7.80mil" at 224.022,183.134 h1.52
  text "4.2" at 240.528,183.134 h1.52
  text "5" at 167.903,180.086 h1.52
  text "Signal Layer 1" at 178.315,180.086 h1.52
  text "Copper" at 202.184,180.086 h1.52
  text "1.40mil" at 224.022,180.086 h1.52
  text "6" at 167.903,177.038 h1.52
  text "Dielectric 2" at 178.315,177.038 h1.52
  text "FR-4" at 202.184,177.038 h1.52
  text "40.00mil" at 224.022,177.038 h1.52
  text "4.2" at 240.528,177.038 h1.52
  text "7" at 167.903,173.99 h1.52
  text "Signal Layer 2" at 178.315,173.99 h1.52
  text "Copper" at 202.184,173.99 h1.52
  text "1.40mil" at 224.022,173.99 h1.52
  text "8" at 167.903,170.942 h1.52
  text "Dielectric 4" at 178.315,170.942 h1.52
  text "7.80mil" at 224.022,170.942 h1.52
  text "4.2" at 240.528,170.942 h1.52
  text "9" at 167.903,167.894 h1.52
  text "Bottom Layer" at 178.315,167.894 h1.52
  text "Copper" at 202.184,167.894 h1.52
  text "1.40mil" at 224.022,167.894 h1.52
  text "10" at 167.903,164.846 h1.52
  text "Bottom Solder" at 178.315,164.846 h1.52
  text "Solder Resist" at 202.184,164.846 h1.52
  text "0.40mil" at 224.022,164.846 h1.52
  text "3.5" at 240.528,164.846 h1.52
  text "11" at 167.903,161.798 h1.52
  text "Bottom Overlay" at 178.315,161.798 h1.52
  text ".Layer_Name" at 14.656,-21.806 h1.52
M13 Component Bodies Top:
  text ".Layer_Name" at 14.656,-21.806 h1.52
M14 Component Bodies Bottom:
  text ".Layer_Name" at 14.656,-21.806 h1.52
M15 Courtyards Top:
  text ".Layer_Name" at 14.656,-21.806 h1.52
M16 Courtyards Bottom:
  text ".Layer_Name" at 14.656,-21.806 h1.52
Drill Drawing:
  circle w0.254: c6.62,148.23 r0.847
  lines w0.254: 5.773,135.953 7.467,135.953 7.467,137.647 5.773,137.647 5.773,135.953 ; 5.773,141.457 7.467,141.457 6.62,139.763 5.773,141.457 ; 5.773,143.573 6.62,143.997 7.467,143.573 7.043,144.42 7.467,145.267 6.62,144.843 5.773,145.267 6.197,144.42 5.773,143.573 ; 5.773,151.617 6.197,151.617 6.62,151.194 7.043,151.617 7.467,151.617 7.043,152.04 7.467,152.463 7.043,152.463 6.62,152.887 6.197,152.463 5.773,152.463 6.197,152.04 5.773,151.617
  lines w0.381: 4.255,134.81 282.662,134.81 ; 4.255,153.861 282.662,153.861 ; 18.247,131 18.247,157.671 ; 31.959,131 31.959,157.671 ; 59.891,131 59.891,157.671 ; 72.74,131 72.74,157.671 ; 91.379,131 91.379,157.671 ; 129.467,131 129.467,157.671 ; 144.45,131 144.45,157.671 ; 163.393,131 163.393,157.671 ; 192.087,131 192.087,157.671 ; 213.772,131 213.772,157.671 ; 247.646,131 247.646,157.671 ; 4.255,131 282.662,131 282.662,157.671 4.255,157.671 4.255,131
  text "Symbol" at 6.54,155.004 h1.83
  text "Count" at 19.39,155.004 h1.83
  text "Hole Size" at 33.102,155.004 h1.83
  text "Plated" at 61.034,155.004 h1.83
  text "Hole Type" at 73.883,155.004 h1.83
  text "Drill Layer Pair" at 92.522,155.004 h1.83
  text "Via/Pad" at 130.61,155.004 h1.83
  text "Pad Shape" at 145.593,155.004 h1.83
  text "Template" at 164.536,155.004 h1.83
  text "Description" at 193.23,155.004 h1.83
  text "Hole Tolerance (+)" at 214.915,155.004 h1.83
  text "Hole Tolerance (-)" at 248.789,155.004 h1.83
  text "4" at 19.39,151.194 h1.52
  text "43.00mil (1.092mm)" at 33.102,151.194 h1.52
  text "PTH" at 61.034,151.194 h1.52
  text "Round" at 73.883,151.194 h1.52
  text "Top Layer - Bottom Layer" at 92.522,151.194 h1.52
  text "Pad" at 130.61,151.194 h1.52
  text "Rounded" at 145.593,151.194 h1.52
  text "c180h109" at 164.536,151.194 h1.52
  text "8" at 19.39,147.383 h1.52
  text "67.00mil (1.702mm)" at 33.102,147.383 h1.52
  text "PTH" at 61.034,147.383 h1.52
  text "Round" at 73.883,147.383 h1.52
  text "Top Layer - Bottom Layer" at 92.522,147.383 h1.52
  text "Pad" at 130.61,147.383 h1.52
  text "Rounded" at 145.593,147.383 h1.52
  text "r229_279h170r100" at 164.536,147.383 h1.52
  text "8" at 19.39,143.573 h1.52
  text "80.00mil (2.032mm)" at 33.102,143.573 h1.52
  text "PTH" at 61.034,143.573 h1.52
  text "Round" at 73.883,143.573 h1.52
  text "Top Layer - Bottom Layer" at 92.522,143.573 h1.52
  text "Pad" at 130.61,143.573 h1.52
  text "Rounded" at 145.593,143.573 h1.52
  text "c254h203" at 164.536,143.573 h1.52
  text "12" at 19.39,139.763 h1.52
  text "33.86mil (0.860mm)" at 33.102,139.763 h1.52
  text "NPTH" at 61.034,139.763 h1.52
  text "Round" at 73.883,139.763 h1.52
  text "Top Layer - Bottom Layer" at 92.522,139.763 h1.52
  text "Pad" at 130.61,139.763 h1.52
  text "Rounded" at 145.593,139.763 h1.52
  text "c56hn86m96(Tol5-0)" at 164.536,139.763 h1.52
  text "1.97mil (0.050mm)" at 214.915,139.763 h1.52
  text "0.00mil (0.000mm)" at 248.789,139.763 h1.52
  text "33" at 19.39,135.953 h1.52
  text "10.00mil (0.254mm)" at 33.102,135.953 h1.52
  text "PTH" at 61.034,135.953 h1.52
  text "Round" at 73.883,135.953 h1.52
  text "Top Layer - Bottom Layer" at 92.522,135.953 h1.52
  text "Via" at 130.61,135.953 h1.52
  text "Rounded" at 145.593,135.953 h1.52
  text "v51h25" at 164.536,135.953 h1.52
  text "65 Total" at 19.39,132.143 h1.52
  text ".Layer_Name" at 14.656,-21.806 h1.52
M17 Embedded Cavity:
  text ".Layer_Name" at 14.656,-21.806 h1.52
M18 Embedded Assembly:
  text ".Layer_Name" at 14.656,-21.806 h1.52
M19 Embedded Keepout:
  text ".Layer_Name" at 14.656,-21.806 h1.52

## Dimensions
0,0 to 0,35.179 on M2 Board Dimensions
0,0 to 0,14.097 on M2 Board Dimensions
34.036,0 to 40.894,15.113 on M2 Board Dimensions
0,0 to 34.036,0 on M2 Board Dimensions
0,-10.16 to 25.4,-10.16 on M2 Board Dimensions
